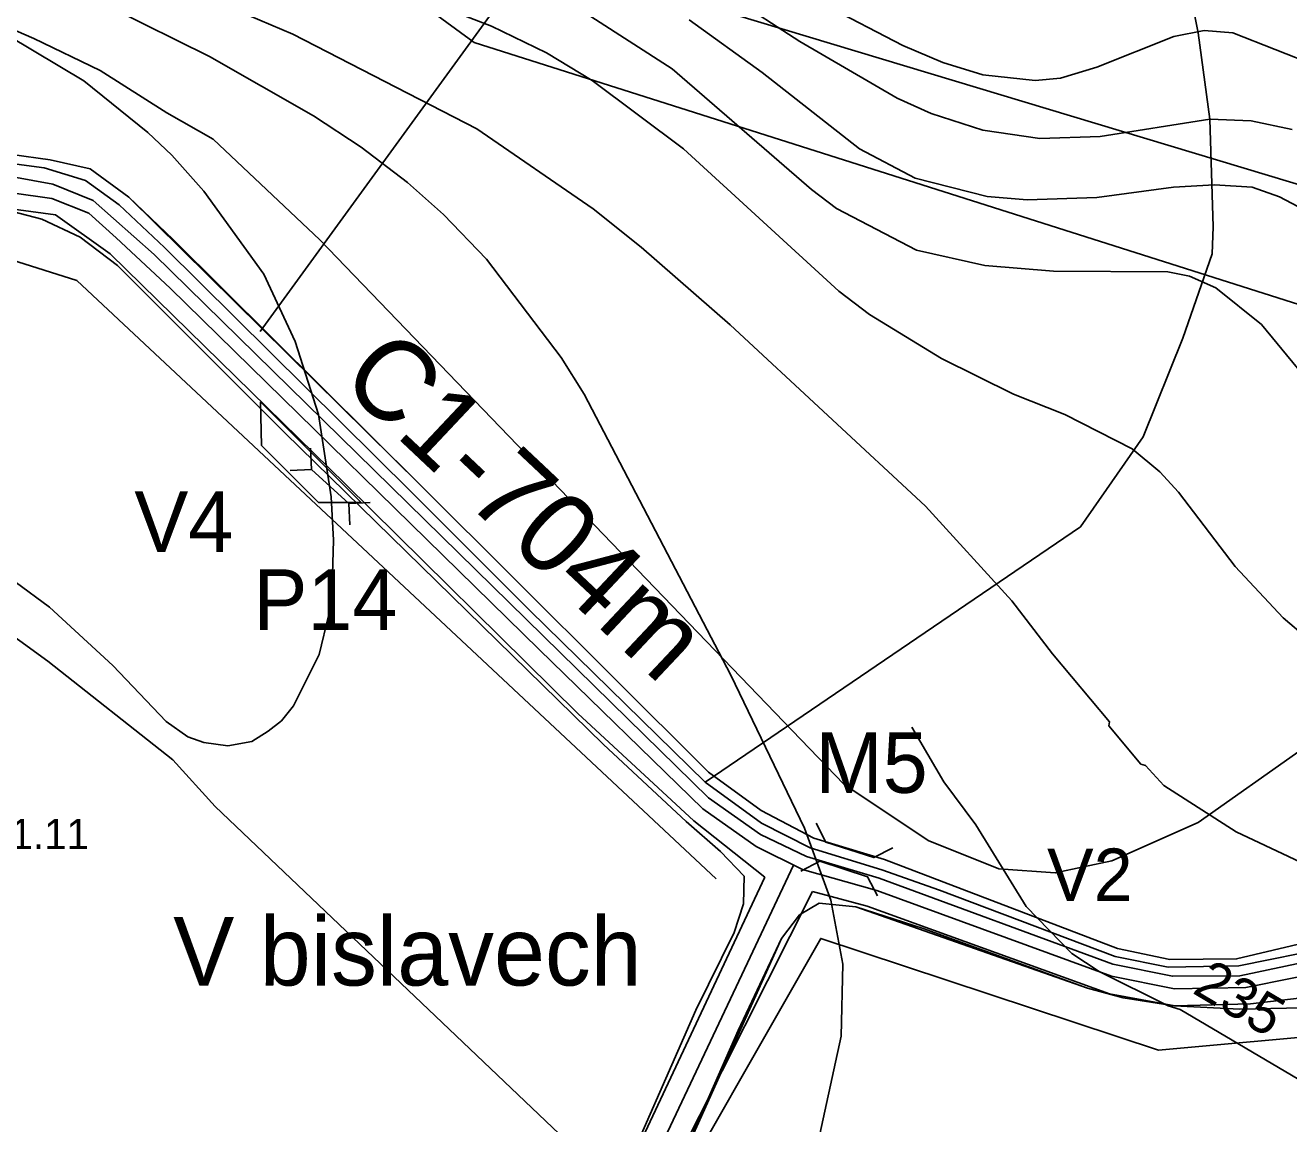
# Model space of a CAD drawing. Extents: x -662500 to -653478, y -1056827 to -1049993.
# Drawn here: x -660921.6 to -660608.1, y -1052555.2 to -1052282.8 of the extents above; entities that cross this region are included whole.
import ezdxf

# ---------------------------------------------------------------- set-up
doc = ezdxf.new("R2010")
doc.units = 0
for name, color, linetype in [('58', 7, 'Continuous'), ('Vrstva 10', 7, 'Continuous'), ('Vrstva 17', 7, 'Continuous'), ('Vrstva 18', 7, 'Continuous'), ('Vrstva 22', 7, 'Continuous'), ('Vrstva 24', 7, 'Continuous'), ('Vrstva 32', 7, 'Continuous'), ('Vrstva 37', 7, 'Continuous'), ('Vrstva 5', 7, 'Continuous'), ('Vrstva 52', 7, 'Continuous'), ('Vrstva 54', 7, 'Continuous'), ('Vrstva 57', 7, 'Continuous'), ('Vrstva 6', 7, 'Continuous'), ('Vrstva 61', 7, 'Continuous'), ('Vrstva 7', 7, 'Continuous')]:
    doc.layers.add(name, color=color, linetype=linetype)

# ---------------------------------------------------------------- blocks, each defined once
blk = doc.blocks.new('PSZ021')
at = {"layer": 'Vrstva 17'}
for points in [[(-10.01, 6.26), (-6.26, 2.51), (6.24, 2.51), (9.99, 6.26)], [(-10.01, -6.24), (-6.26, -2.49), (6.24, -2.49), (9.99, -6.24)]]:
    blk.add_lwpolyline(points, dxfattribs=at)

msp = doc.modelspace()

# ---------------------------------------------------------------- linework, layer by layer
at = {"layer": 'Vrstva 10'}
for points in [[(-660546.11, -1052497.85), (-660561.7, -1052504), (-660578.32, -1052510.55), (-660595.68, -1052516.79), (-660618.72, -1052521.45), (-660636.38, -1052521.76), (-660652.06, -1052518.66), (-660710.31, -1052497.41), (-660728.73, -1052492.17), (-660740.25, -1052486.46), (-660753.47, -1052477.11), (-660794.06, -1052437.58), (-660885.6, -1052347.94), (-660899.02, -1052335.46), (-660905.85, -1052329.39), (-660915, -1052325.75), (-660962.95, -1052318.91), (-661017.59, -1052309.83), (-661090.6, -1052300.47), (-661112.94, -1052298), (-661139.03, -1052295.19), (-661149.56, -1052294.54), (-661166.15, -1052294.53)], [(-660730.96, -1052491.07), (-660742.4, -1052515.29), (-660772.11, -1052578.35), (-660776.37, -1052584.21), (-660783.83, -1052592.29), (-660801.06, -1052607.48), (-660807.81, -1052615.02), (-660821.93, -1052631.99), (-660831.3, -1052641.31), (-660872.41, -1052674.97), (-660929.03, -1052716.48), (-660971.55, -1052741.79), (-660975.1, -1052744.68)]]:
    msp.add_lwpolyline(points, dxfattribs=at)
at = {"layer": 'Vrstva 17'}
msp.add_lwpolyline([(-660738.08, -1052494.07), (-660755.67, -1052480.13), (-660784.46, -1052453.47), (-660842.13, -1052396.61), (-660900.5, -1052339.47), (-660914.09, -1052329.74), (-660943.55, -1052325.84), (-660957.14, -1052326.63), (-660973.12, -1052322.11), (-661027.37, -1052311.93), (-661136.92, -1052298.89), (-661163.72, -1052298.84)], dxfattribs=at)
at = {"layer": 'Vrstva 22'}
msp.add_lwpolyline([(-661110.22, -1052170.21), (-661096.01, -1052128.52), (-660487.99, -1052312.15), (-660506.09, -1052352.23)], close=True, dxfattribs=at)
at = {"layer": 'Vrstva 24'}
for points in [[(-660157, -1052384), (-660277.5, -1052378.5), (-660368.5, -1052369.5), (-660424, -1052367.5), (-660486.5, -1052376), (-660524.5, -1052389), (-660555, -1052408.5), (-660605, -1052462.5), (-660630.5, -1052480.5), (-660652, -1052490), (-660666, -1052493), (-660680, -1052492), (-660697.5, -1052485), (-660718.5, -1052471), (-660848.5, -1052336), (-660875, -1052311), (-660886.5, -1052304.5), (-660903, -1052294), (-660919.5, -1052286), (-660980.5, -1052259.5)], [(-660772, -1052574), (-660874.5, -1052476.5), (-660885, -1052465), (-660916, -1052440.5), (-660936, -1052426), (-660954.5, -1052417.5), (-660980.5, -1052408), (-661038, -1052393), (-661089.5, -1052368.5), (-661136, -1052338), (-661184, -1052312.5), (-661189, -1052307)]]:
    msp.add_lwpolyline(points, dxfattribs=at)
at = {"layer": 'Vrstva 32'}
msp.add_lwpolyline([(-660546.87, -1052493.9), (-660575.8, -1052504.06), (-660597.57, -1052511.43), (-660620.47, -1052516.09), (-660637.98, -1052516.42), (-660651.15, -1052513.72), (-660694.75, -1052497.27), (-660709.02, -1052492.25), (-660726.82, -1052486.8), (-660738.93, -1052480.67), (-660752.84, -1052470.52), (-660796.36, -1052427.9), (-660825.81, -1052398.45), (-660887, -1052337.91), (-660898.29, -1052327.28), (-660906.63, -1052321.22), (-660916.94, -1052318.12), (-660981.82, -1052309.53), (-661052.17, -1052300.12), (-661122.61, -1052290.71), (-661156.97, -1052286.46), (-661171.41, -1052282.84)], dxfattribs=at)
at = {"layer": 'Vrstva 37'}
msp.add_lwpolyline([(-660920.61, -1052206.16), (-660810.17, -1052287.05), (-660506.62, -1052383.42), (-660536.22, -1052464.9), (-660540.27, -1052493.39), (-660540.27, -1052503.48), (-660534.66, -1052516.97), (-660434.32, -1052493.61), (-660230.57, -1052568.54), (-660284.32, -1052681.97), (-660363.46, -1052667.73), (-660573.1, -1052736.64), (-660686.93, -1052879.97)], dxfattribs=at)
at = {"layer": 'Vrstva 5'}
for points in [[(-660402.29, -1052259.33), (-660408.77, -1052283.62), (-660433.93, -1052352.12), (-660484.24, -1052323.36), (-660515.63, -1052387.13), (-660552.99, -1052463.61), (-660546.04, -1052495.02), (-660552.69, -1052492.35), (-660575.76, -1052501.21), (-660598.28, -1052508.95), (-660621.02, -1052514.33), (-660637.54, -1052514.46), (-660650.58, -1052511.74), (-660708.39, -1052489.69), (-660725.92, -1052484.38), (-660738.96, -1052477.51), (-660752.07, -1052468), (-660823.62, -1052396.74), (-660884.87, -1052335.9), (-660895.91, -1052325.38), (-660905.47, -1052318.35), (-660915.41, -1052316.17), (-660963.02, -1052309.52)], [(-660598.28, -1052508.95), (-660621.02, -1052514.33), (-660637.54, -1052514.46), (-660650.58, -1052511.74), (-660708.39, -1052489.69), (-660725.92, -1052484.38), (-660738.96, -1052477.51), (-660752.07, -1052468), (-660823.62, -1052396.74), (-660895.91, -1052325.38), (-660905.47, -1052318.35), (-660915.41, -1052316.17), (-660963.02, -1052309.52)], [(-660929.69, -1052319.45), (-660914.79, -1052322.15), (-660904.73, -1052326.23), (-660889.63, -1052339.64), (-660772.05, -1052454.81), (-660752.09, -1052474.35), (-660739.16, -1052483.49), (-660727.72, -1052488.92), (-660709.7, -1052494.3), (-660651.74, -1052515.68), (-660636.93, -1052518.65), (-660620.19, -1052518.5), (-660597.5, -1052513.73)], [(-660597.5, -1052513.73), (-660620.19, -1052518.5), (-660636.93, -1052518.65), (-660651.74, -1052515.68), (-660709.7, -1052494.3), (-660727.72, -1052488.92), (-660739.16, -1052483.49), (-660752.09, -1052474.35), (-660772.05, -1052454.81), (-660889.63, -1052339.64), (-660904.73, -1052326.23), (-660914.79, -1052322.15), (-660929.69, -1052319.45)], [(-660928.32, -1052328.06), (-660917.49, -1052330.86), (-660907.97, -1052335.35), (-660898.69, -1052342.31), (-660857.15, -1052383.85), (-660778.08, -1052461.12), (-660757.6, -1052480.26), (-660749.09, -1052487.66), (-660743.24, -1052493.84), (-660743.39, -1052500.66), (-660745.7, -1052507.75), (-660755.18, -1052527.06), (-660775.44, -1052573.22), (-660780.95, -1052583.18), (-660789.17, -1052591), (-660805.31, -1052603.95), (-660810.6, -1052609.41), (-660818.19, -1052616.74), (-660826.8, -1052628.64), (-660839.31, -1052640.39), (-660876.46, -1052670.55), (-660899.32, -1052687.63), (-660925.98, -1052706.8)], [(-660928.32, -1052328.06), (-660917.49, -1052330.86), (-660907.97, -1052335.35), (-660898.69, -1052342.31), (-660857.15, -1052383.85), (-660778.08, -1052461.12), (-660757.6, -1052480.26), (-660749.09, -1052487.66), (-660743.24, -1052493.84), (-660743.39, -1052500.66), (-660745.7, -1052507.75), (-660755.18, -1052527.06), (-660775.44, -1052573.22), (-660780.95, -1052583.18), (-660789.17, -1052591), (-660805.31, -1052603.95), (-660818.19, -1052616.74), (-660826.8, -1052628.64), (-660839.31, -1052640.39), (-660876.46, -1052670.55), (-660899.32, -1052687.63), (-660925.98, -1052706.8)], [(-660963.87, -1052742.7), (-660920.45, -1052716.01), (-660892.53, -1052696.06), (-660874.07, -1052682.42), (-660835.01, -1052650.9), (-660809.61, -1052627.89), (-660804.83, -1052625.49), (-660809.42, -1052621.74), (-660801.02, -1052611.14), (-660782.55, -1052594.75), (-660776.11, -1052588.25), (-660771.96, -1052582.87), (-660769.37, -1052586.51), (-660765.45, -1052579.22), (-660733.95, -1052509.32), (-660729.44, -1052503.44), (-660724.58, -1052500.5), (-660715.51, -1052501.44), (-660658.01, -1052521.57), (-660649.17, -1052523.99), (-660636.46, -1052526.02), (-660620.21, -1052526.77), (-660597.01, -1052526.32)], [(-660765.45, -1052579.22), (-660744.66, -1052532.13), (-660733.95, -1052509.32), (-660729.44, -1052503.44), (-660724.58, -1052500.5), (-660715.51, -1052501.44), (-660698.76, -1052506.81), (-660658.01, -1052521.57), (-660649.17, -1052523.99), (-660636.46, -1052526.02), (-660620.21, -1052526.77), (-660597.01, -1052526.32)]]:
    msp.add_lwpolyline(points, dxfattribs=at)
at = {"layer": 'Vrstva 52'}
msp.add_lwpolyline([(-660768.57, -1052587.01), (-660724.21, -1052509.24), (-660640.37, -1052537), (-660593.93, -1052532.78), (-660534.66, -1052516.97)], dxfattribs=at)
at = {"layer": 'Vrstva 54'}
msp.add_lwpolyline([(-660750.17, -1052494.49), (-660908.76, -1052346.08), (-660941.33, -1052335.81), (-660994.5, -1052328.6), (-661141.48, -1052305.44)], dxfattribs=at)
at = {"layer": 'Vrstva 57'}
for points in [[(-660614.7, -1052146.79), (-660670.16, -1052156.66), (-660702.59, -1052170.76), (-660725.62, -1052188.62), (-660759.45, -1052215.88), (-660863.32, -1052358.75)], [(-660615.41, -1052161.36), (-660626.92, -1052180.39), (-660637.73, -1052198.72), (-660641.26, -1052211.41), (-660639.38, -1052249.95), (-660634.68, -1052263.7), (-660630.57, -1052284.61), (-660627.61, -1052306.06), (-660626.81, -1052332.78), (-660627.04, -1052339.48), (-660634.33, -1052360.39), (-660644.19, -1052384.83), (-660659.7, -1052407.15), (-660752.84, -1052470.52)]]:
    msp.add_lwpolyline(points, dxfattribs=at)
at = {"layer": 'Vrstva 6'}
msp.add_lwpolyline([(-660462.36, -1052329.02), (-660459.17, -1052336.8), (-660433.93, -1052352.12), (-660409.6, -1052285.62), (-660402.29, -1052259.33), (-660394.65, -1052237.63), (-660389.99, -1052217.3), (-660417.67, -1052208.59), (-660421.03, -1052221.2), (-660428.58, -1052243.68), (-660452.47, -1052238.38), (-660475.36, -1052232.69), (-660499.48, -1052225.45), (-660495.07, -1052211.29), (-660578.14, -1052190.03), (-660563.85, -1052144.19), (-660586.5, -1052144.05), (-660704.06, -1052109.9), (-660743.35, -1052235.04), (-661096.01, -1052128.52), (-661110.22, -1052170.21), (-660506.09, -1052352.23), (-660487.99, -1052312.15)], close=True, dxfattribs=at)
at = {"layer": 'Vrstva 61'}
msp.add_lwpolyline([(-660838.24, -1052401.1), (-660848.84, -1052401.11), (-660863, -1052386.98), (-660863.2, -1052376.19)], close=True, dxfattribs=at)
for points in [[(-660850.84, -1052387.67), (-660850.57, -1052392.97), (-660855.87, -1052393.23)], [(-660850.57, -1052392.97), (-660841.3, -1052401.36)], [(-660836.01, -1052401.09), (-660841.3, -1052401.36), (-660841.04, -1052406.65)], [(-660738.08, -1052494.07), (-660777.88, -1052578.81), (-660800.49, -1052601.16), (-660813.62, -1052614.14), (-660834.28, -1052637.91), (-660925.3, -1052708.08), (-660970.85, -1052736.56)], [(-660726.22, -1052497.62), (-660765.46, -1052575.43), (-660771.92, -1052586.13), (-660808.78, -1052624.64), (-660828.23, -1052644.96), (-660919.18, -1052715.59), (-660965.2, -1052744.53)], [(-660551.71, -1052504.81), (-660592.72, -1052522.6), (-660617.53, -1052525.5), (-660636.3, -1052525.96), (-660652.58, -1052523.01), (-660712.69, -1052501.28), (-660726.22, -1052497.62)]]:
    msp.add_lwpolyline(points, dxfattribs=at)
at = {"layer": 'Vrstva 7'}
for p, q in [((-660729.36, -1052286.79), (-660770.03, -1052260.43)), ((-660898.85, -1052266.38), (-660855.2, -1052284.95)), ((-660852.65, -1052264.96), (-660805.89, -1052282.96)), ((-660900.27, -1052278.43), (-660875.89, -1052290.47)), ((-660900.27, -1052278.43), (-660875.89, -1052290.47)), ((-660703.85, -1052287.78), (-660723.27, -1052277.72)), ((-660781.23, -1052280.55), (-660761.1, -1052293.59)), ((-660738.71, -1052294.44), (-660756.85, -1052281.4)), ((-660925.78, -1052285.37), (-660907.07, -1052296.57)), ((-660855.2, -1052284.95), (-660809.57, -1052308.47)), ((-660805.89, -1052282.96), (-660792.28, -1052289.62)), ((-660636.54, -1052285.51), (-660655.67, -1052293.16)), ((-660629.02, -1052284.09), (-660636.54, -1052285.51)), ((-660621.94, -1052284.66), (-660629.02, -1052284.09)), ((-660584.53, -1052299.4), (-660621.94, -1052284.66)), ((-660705.27, -1052300.82), (-660729.36, -1052286.79)), ((-660693.93, -1052292.03), (-660703.85, -1052287.78)), ((-660875.89, -1052290.47), (-660850.1, -1052305.21)), ((-660875.89, -1052290.47), (-660850.1, -1052305.21)), ((-660792.28, -1052289.62), (-660780.94, -1052296.42)), ((-660684.01, -1052295.01), (-660693.93, -1052292.03)), ((-660761.1, -1052293.59), (-660726.52, -1052323.49)), ((-660714.62, -1052313.43), (-660738.71, -1052294.44)), ((-660670.97, -1052296.42), (-660684.01, -1052295.01)), ((-660655.67, -1052293.16), (-660664.74, -1052295.86)), ((-660907.07, -1052296.57), (-660891.2, -1052309.32)), ((-660780.94, -1052296.42), (-660758.27, -1052313.43)), ((-660664.74, -1052295.86), (-660670.97, -1052296.42)), ((-660696.76, -1052304.64), (-660705.27, -1052300.82)), ((-660684.01, -1052308.75), (-660696.76, -1052304.64)), ((-660850.1, -1052305.21), (-660838.2, -1052313.01)), ((-660850.1, -1052305.21), (-660838.2, -1052313.01)), ((-660627.61, -1052306.06), (-660654.82, -1052310.31)), ((-660617.4, -1052306.49), (-660627.61, -1052306.06)), ((-660607.2, -1052308.61), (-660617.4, -1052306.49)), ((-660891.2, -1052309.32), (-660885.25, -1052314.99)), ((-660809.57, -1052308.47), (-660780.66, -1052328.31)), ((-660669.84, -1052310.88), (-660684.01, -1052308.75)), ((-660654.82, -1052310.31), (-660669.84, -1052310.88)), ((-660838.2, -1052313.01), (-660826.72, -1052321.79)), ((-660838.2, -1052313.01), (-660826.72, -1052321.79)), ((-660758.27, -1052313.43), (-660719.72, -1052348.72)), ((-660700.73, -1052320.66), (-660714.62, -1052313.43)), ((-660885.25, -1052314.99), (-660877.31, -1052323.92)), ((-660826.72, -1052321.79), (-660817.79, -1052329.73)), ((-660826.72, -1052321.79), (-660817.79, -1052329.73)), ((-660726.52, -1052323.49), (-660720.29, -1052328.17)), ((-660682.88, -1052325.19), (-660700.73, -1052320.66)), ((-660636.68, -1052322.93), (-660655.67, -1052325.48)), ((-660626.47, -1052322.36), (-660636.68, -1052322.93)), ((-660617.12, -1052322.93), (-660626.47, -1052322.36)), ((-660610.32, -1052325.33), (-660617.12, -1052322.93)), ((-660877.31, -1052323.92), (-660862.43, -1052344.47)), ((-660672.96, -1052326.04), (-660682.88, -1052325.19)), ((-660655.67, -1052325.48), (-660672.96, -1052326.04)), ((-660605.78, -1052327.74), (-660610.32, -1052325.33)), ((-660817.79, -1052329.73), (-660807.16, -1052340.78)), ((-660817.79, -1052329.73), (-660807.16, -1052340.78)), ((-660780.66, -1052328.31), (-660768.76, -1052337.8)), ((-660720.29, -1052328.17), (-660700.45, -1052338.51)), ((-660768.76, -1052337.8), (-660746.65, -1052357.08)), ((-660700.45, -1052338.51), (-660683.44, -1052342.34)), ((-660807.16, -1052340.78), (-660788.6, -1052365.16)), ((-660807.16, -1052340.78), (-660788.6, -1052365.16)), ((-660683.44, -1052342.34), (-660666.44, -1052343.76)), ((-660862.43, -1052344.47), (-660854.64, -1052361.19)), ((-660666.44, -1052343.76), (-660638.09, -1052343.9)), ((-660638.09, -1052343.9), (-660632.71, -1052345.03)), ((-660632.71, -1052345.03), (-660626.19, -1052347.87)), ((-660719.72, -1052348.72), (-660712.07, -1052354.53)), ((-660626.19, -1052347.87), (-660614.85, -1052356.94)), ((-660712.07, -1052354.53), (-660694.21, -1052365.44)), ((-660746.65, -1052357.08), (-660698.18, -1052402)), ((-660614.85, -1052356.94), (-660605.92, -1052367.85)), ((-660854.64, -1052361.19), (-660848.83, -1052379.33)), ((-660788.6, -1052365.16), (-660782.93, -1052374.23)), ((-660788.6, -1052365.16), (-660782.93, -1052374.23)), ((-660694.21, -1052365.44), (-660676.36, -1052374.23)), ((-660782.93, -1052374.23), (-660746.51, -1052443.95)), ((-660782.93, -1052374.23), (-660746.51, -1052443.95)), ((-660676.36, -1052374.23), (-660663.6, -1052379.33)), ((-660848.83, -1052379.33), (-660845.71, -1052399.74)), ((-660663.6, -1052379.33), (-660646.88, -1052387.83)), ((-660646.88, -1052387.83), (-660640.08, -1052393.5)), ((-660640.08, -1052393.5), (-660635.4, -1052398.6)), ((-660635.4, -1052398.6), (-660621.37, -1052417.02)), ((-660845.71, -1052399.74), (-660845.14, -1052410.51)), ((-660698.18, -1052402), (-660676.78, -1052425.53)), ((-660845.14, -1052410.51), (-660845.43, -1052421.84)), ((-660621.37, -1052417.02), (-660609.47, -1052429.78)), ((-660915.58, -1052427.09), (-660924.08, -1052420.85)), ((-660845.43, -1052421.84), (-660846.28, -1052428.93)), ((-660899.84, -1052441.54), (-660915.58, -1052427.09)), ((-660676.78, -1052425.53), (-660666.72, -1052438.71)), ((-660846.28, -1052428.93), (-660848.68, -1052438.85)), ((-660609.47, -1052429.78), (-660603.37, -1052434.88)), ((-660848.68, -1052438.85), (-660855.06, -1052451.6)), ((-660666.72, -1052438.71), (-660652.55, -1052455.57)), ((-660886.66, -1052455.43), (-660899.84, -1052441.54)), ((-660746.51, -1052443.95), (-660728.22, -1052481.93)), ((-660746.51, -1052443.95), (-660728.22, -1052481.93)), ((-660855.06, -1052451.6), (-660858.04, -1052455.29)), ((-660858.04, -1052455.29), (-660861.3, -1052457.84)), ((-660881.28, -1052459.26), (-660886.66, -1052455.43)), ((-660861.3, -1052457.84), (-660865.41, -1052460.39)), ((-660701.58, -1052456.85), (-660693.65, -1052470.45)), ((-660652.55, -1052455.57), (-660652.69, -1052456.56)), ((-660652.69, -1052456.56), (-660644.75, -1052466.06)), ((-660877.31, -1052460.67), (-660881.28, -1052459.26)), ((-660871.36, -1052461.52), (-660877.31, -1052460.67)), ((-660865.41, -1052460.39), (-660871.36, -1052461.52)), ((-660644.75, -1052466.06), (-660643.62, -1052466.34)), ((-660643.62, -1052466.34), (-660639.09, -1052471.3)), ((-660693.65, -1052470.45), (-660685.71, -1052481.08)), ((-660639.09, -1052471.3), (-660621.09, -1052482.78)), ((-660728.22, -1052481.93), (-660721.71, -1052499.79)), ((-660728.22, -1052481.93), (-660721.71, -1052499.79)), ((-660685.71, -1052481.08), (-660673.24, -1052501.35)), ((-660621.09, -1052482.78), (-660596.71, -1052494.4)), ((-660721.71, -1052499.79), (-660718.73, -1052515.66)), ((-660721.71, -1052499.79), (-660718.73, -1052515.66)), ((-660673.24, -1052501.35), (-660661.9, -1052512.97)), ((-660661.9, -1052512.97), (-660655.1, -1052517.5)), ((-660718.73, -1052515.66), (-660719.16, -1052533.52)), ((-660718.73, -1052515.66), (-660719.16, -1052533.52)), ((-660655.1, -1052517.5), (-660637.95, -1052526)), ((-660637.95, -1052526), (-660634.98, -1052526.85)), ((-660634.98, -1052526.85), (-660595.3, -1052550.38)), ((-660719.16, -1052533.52), (-660728.79, -1052578.02)), ((-660719.16, -1052533.52), (-660728.79, -1052578.02))]:
    msp.add_line(p, q, dxfattribs=at)

# ---------------------------------------------------------------- block references
at = {"layer": 'Vrstva 17', "rotation": -17.80451207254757}
msp.add_blockref('PSZ021', (-660717.74, -1052489.68), dxfattribs=at)

# ---------------------------------------------------------------- texts
at = {"layer": '58'}
msp.add_text('V bislavech', height=17, dxfattribs=at).set_placement((-660884.88, -1052520.94))
at = {"layer": 'Vrstva 17'}
msp.add_text('M5', height=15, rotation=360, dxfattribs=at).set_placement((-660725.53, -1052473.15))
at = {"layer": 'Vrstva 18'}
msp.add_text('C1-704m', height=20, rotation=316.7239, dxfattribs=at).set_placement((-660844.08, -1052371.21))
at = {"layer": 'Vrstva 24'}
msp.add_text('3.51.11', height=7.5, dxfattribs=at).set_placement((-660939.22, -1052487.11))
at = {"layer": 'Vrstva 32'}
msp.add_text('V2', height=13, rotation=360, dxfattribs=at).set_placement((-660668.06, -1052499.97))
at = {"layer": 'Vrstva 61'}
for s, p in [('V4', (-660894.52, -1052413.4)), ('P14', (-660864.96, -1052432.72))]:
    msp.add_text(s, height=15, dxfattribs=at).set_placement(p)
at = {"layer": 'Vrstva 7'}
msp.add_text('235', height=10, rotation=329.3383, dxfattribs=at).set_placement((-660632.28, -1052522.64))

doc.saveas('drawing.dxf')
